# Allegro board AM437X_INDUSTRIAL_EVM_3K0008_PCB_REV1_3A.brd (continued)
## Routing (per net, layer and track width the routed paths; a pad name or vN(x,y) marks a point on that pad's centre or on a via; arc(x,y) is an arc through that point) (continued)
AM437X_MMC0_DAT3: length 77.9
  TOP w0.13: v1(71.12,59.69) 71.77,59.04 72.81,59.04 73.12,59.35 U11.B1 ; v1(73.79,11) 74.5,10.29 R239.1 ; v1(65.91,56.22) 65.57,55.88 65.15,55.88 63.88,54.61 R158.2
  L4_SIG2 w0.13: v1(79.48,10.64) 79.98,11.15 79.98,17.7 73.48,24.2 72.96,24.2 69.34,27.82 68.61,27.82 67.11,29.31 67.11,29.94 67.22,30.04 67.22,32.39 65.87,33.74 65.87,39.25 65.18,39.94 63.23,39.94 61.04,42.13 61.04,48.44 65.53,52.93 65.53,55.84 v1(65.91,56.22) 65.91,56.31 69.29,59.69 v1(71.12,59.69)
  BOTTOM w0.13: v1(73.79,11) 74.14,10.64 v1(79.48,10.64)
AM437X_MMC0_SDCD: length 9.1
  TOP w0.13: R84.2 83.31,82.68 83.31,80.01 83.19,79.88 83.19,78.99 82.29,78.1 82.29,77.59 82.28,77.58 82.28,75.63 81.78,75.14 U11.R25
AM437X_OSC0_IN: length 9.4
  TOP w0.13: R92.1 73.02,82.55 73.02,79.86 74.84,78.04 74.84,76.12 73.98,75.27 U11.C25
AM437X_OSC0_OUT: length 9.5
  TOP w0.13: U11.B25 74.6,76.22 74.6,77.95 74.12,78.43 72.48,80.07 R91.1
AM437X_PROFI_RXD: length 117.2
  TOP w0.13: v1(83.95,7.34) 82.85,7.34 J16.47 ; U11.K21 78.26,72.35 v1(78.09,72.52)
  L4_SIG2 w0.13: v1(78.08,81.67) 78.56,81.19 78.56,80.96 79.76,79.76 79.76,78.66 82.35,76.07 82.76,76.07 84.7,74.13 86.97,74.13 91.35,69.75 91.35,65.57 93.55,63.37 93.55,62.53 97.05,59.03 97.05,56.18 98.72,54.51 98.72,53.66 100.07,52.32 100.07,50.94 101.61,49.4 101.61,40.33 103.04,38.91 103.2,38.91 103.83,38.28 103.83,34.65 103.98,34.5 103.98,27 103.07,26.08 103.07,13.47 102.9,13.3 102.9,12.56 100.88,10.54 100.88,9.67 100.36,9.14 97.35,9.14 97.17,9.33 93.7,9.33 93.11,8.74 85.34,8.74 v1(83.95,7.34)
  BOTTOM w0.13: v1(78.08,81.67) 78.08,79.64 78.1,79.63 78.1,77 77.81,76.72 77.81,75.63 78.45,75 78.45,72.88 v1(78.09,72.52)
AM437X_PROFI_TXD: length 153.2
  TOP w0.13: U11.L21 79.4,72.35 v1(79.63,72.12)
  L3_SIG1 w0.13: v1(82.93,86.36) 82.93,84.33 82.68,84.07 82.68,82.57 83.46,81.78 83.46,80.47 83.24,80.24 83.24,79.04 80.64,76.45 80.64,72.39 80.38,72.12 v1(79.63,72.12)
  L4_SIG2 w0.13: v1(82.93,86.36) 83.06,86.36 85.78,83.64 86.03,83.64 88.23,81.44 91.68,81.44 92.4,80.72 92.4,80.72 97.42,75.7 97.42,72.91 98.34,71.99 98.34,67.91 99.35,66.9 99.35,64.94 100.07,64.22 102.48,64.22 103.18,63.52 103.36,63.52 106.17,60.71 108.31,60.71 110.44,58.58 110.44,55.71 110.04,55.31 110.04,54.83 110.98,53.9 110.98,50.04 111.97,49.05 111.97,45.91 112.54,45.34 112.54,37 113.85,35.69 113.85,34.57 115.86,32.56 115.86,29.11 111.2,24.45 110.81,24.06 110.81,21.07 109.76,20.02 109.76,8 110.33,7.44 110.33,3.44 109.58,2.69 93.07,2.69 92.33,3.43 92.33,6.35 91.62,7.06 84.57,7.06 J16.45
AM437X_PRU0_ENDAT0_CLK: length 27.8
  TOP w0.13: U11.N24 80.17,74.62 80.17,75.18 80.92,75.93 80.92,81.23 81.35,81.66 v1(81.35,81.91)
  L4_SIG2 w0.13: v2(87.63,77.6) 87.12,77.09 84.46,77.09 81.35,80.19 v1(81.35,81.91)
  BOTTOM w0.13: R427.2 R428.2 94.35,77.1 92.2,79.25 89.28,79.25 v2(87.63,77.6)
AM437X_PRU0_ENDAT0_OUT: length 18.3
  TOP w0.13: v1(81.6,73.47) 81.39,73.47 81.24,73.32 80.81,73.32 U11.N22
  L4_SIG2 w0.13: v2(86.87,77.6) 84.39,77.6 84.08,77.9 82.24,79.75 82.24,80.04 v1(81.89,80.39)
  BOTTOM w0.13: v2(86.87,77.6) 86.87,78.23 86.48,78.62 R422.2 R423.2 ; v1(81.89,80.39) 81.89,80.39 81.89,76.38 81.37,75.85 81.37,73.7 v1(81.6,73.47)
AM437X_PRU0_ENDAT0_OUTEN: length 215.6
  TOP w0.13: U11.H23 76.83,73.65 v1(76.66,73.48)
  L3_SIG1 w0.13: J16.35 94.33,4.86 94.33,3.44 93.51,2.62 68.86,2.62 66.45,5.03 62.56,5.03 61.08,3.55 54.05,3.55 53.37,2.86 48.5,2.86 47.61,3.75 42.48,3.75 40.13,6.1 28.01,6.1 25.3,8.81 25.3,13.41 32.38,20.49 v1(32.38,24.77)
  L4_SIG2 w0.13: v1(100.1,10.03) 100.1,11.37 102.45,13.72 102.45,26.34 103.37,27.25 103.37,33.59 102.35,34.61 102.35,38.73 100.99,40.08 100.99,49.14 99.45,50.68 99.45,52.06 98.11,53.41 98.11,54.25 96.43,55.93 96.43,58.78 92.93,62.28 92.93,63.12 90.73,65.32 90.73,69.09 87.4,72.42 87.01,72.42 86.66,72.76 86.66,73.42 86.41,73.67 84.5,73.67 82.66,75.52 80.85,75.52 78.36,78 v1(76.61,78)
  BOTTOM w0.13: v1(100.1,10.03) 100.99,9.14 101.75,9.14 102.13,8.76 102.13,7.85 101.57,7.29 98.93,7.29 98.6,6.96 94.46,6.96 J16.35 ; v1(32.38,24.77) 31.62,25.53 28.58,25.53 27.18,24.13 18.3,24.13 R526.2 ; v1(76.61,78) 76.66,77.95 v1(76.66,73.48)
AM437X_PRUETH0_COL: length 95.3
  TOP w0.13: v1(75.29,81.15) 74.93,80.8 74.93,79.54 75.3,79.17 75.3,75.93 74.64,75.27 U11.D25
  L3_SIG1 w0.13: v1(70.31,100.28) 70.68,100.65 70.68,102.83 70.19,103.32 69.63,103.32 65.82,107.13 61.66,107.13 58.68,104.15 44.62,104.15 43.1,105.66 29.72,105.66 v1(28.83,106.55)
  BOTTOM w0.13: v1(75.29,81.15) 75.29,81.79 75,82.07 75,83.97 74.28,84.69 74.28,85.94 69.9,90.32 69.9,99.88 v1(70.31,100.28) ; R351.2 33.27,91.57 32.1,91.57 31.69,91.97 31.69,92.99 30.61,94.07 30.61,101.6 28.83,103.38 v1(28.83,106.55)
AM437X_PRUETH0_CRS: length 65.9
  TOP w0.13: v1(76.15,72.13) 76.58,71.7 U11.G20 ; R65.2 v1(34.61,88.61)
  L3_SIG1 w0.13: v1(66.49,71.44) 66.54,71.44 66.54,71.48 66.47,71.48 66.47,71.43 66.47,71.43 65.81,72.09 65.13,72.09 63.4,70.36 61.56,70.36 59.28,68.07 57.44,68.07 56.84,68.67 56.17,68.67 54.49,70.35 54.23,70.35 50.49,74.08 47.58,74.08 44.71,76.95 35.06,76.95 v1(33.02,78.99)
  L4_SIG2 w0.13: v1(76.15,72.13) 76.12,72.16 76.12,73.48 75.17,74.44 74.37,74.44 72.26,72.33 67.32,72.33 66.49,71.49 v1(66.49,71.44)
  BOTTOM w0.13: v1(33.02,78.99) 33.38,78.99 34.24,79.85 34.24,80.36 36.17,82.29 36.17,83.24 34.81,84.59 34.81,88.41 v1(34.61,88.61)
AM437X_PRUETH0_MRCLK: length 87.2
  TOP w0.13: U11.C17 74.28,70.05 v1(74.28,70.16) ; v1(42.34,100.1) 42.34,90.98 40.89,89.53 36.45,89.53 35.69,88.77 35.69,87.63 34.42,86.36 R76.2
  L3_SIG1 w0.13: v1(61.62,89.36) 61.77,89.51 61.77,90.24 59.49,92.52 59.49,93.89 58.48,94.9 58.48,96.26 57.39,97.35 57.39,97.48 56.72,98.16 55.26,98.16 52.94,100.47 50.96,100.47 50.19,99.69 47.17,99.69 46.65,100.22 44.61,100.22 44.5,100.1 v1(42.34,100.1)
  L4_SIG2 w0.13: v1(61.62,89.36) 61.54,89.36 59.72,87.54 59.72,79.28 v1(58.29,77.85)
  BOTTOM w0.13: v1(74.28,70.16) 74.15,70.03 69.67,70.03 66.47,73.23 62.57,73.23 62.07,72.73 57.62,72.73 56.32,74.03 56.09,74.26 56.09,76.28 57.66,77.85 v1(58.29,77.85) ; U39.16 61.73,89.46 v1(61.62,89.36)
AM437X_PRUETH0_RXD0: length 88.2
  TOP w0.13: U11.B18 73.01,70.73 69.48,70.73 69.47,70.73 65.65,74.56 65.01,74.56 64.47,75.11 62.45,75.11 62.03,75.52 60.73,75.52 60.42,75.83 56.15,75.83 55.65,75.34 49.05,75.34 47.83,76.56 47.83,83.59 51.64,87.4 53.37,87.4 55.38,89.42 55.38,89.64 55.81,90.07 56.42,90.07 v1(58.42,92.06)
  L3_SIG1 w0.13: v1(58.42,92.06) 58.42,92.18 56.01,94.59 56.01,95.12 54.42,96.71 54.07,96.71 53.01,97.76 49.48,97.76 49,97.29 43.26,97.29 42.28,98.27 40.31,98.27 39.7,97.66 34.19,97.66 33.28,96.76 33.28,95.76 33.48,95.57 33.54,95.5 34.99,94.06 34.99,93.22 35.64,92.57 35.64,92.53 v1(35.86,92.3)
  BOTTOM w0.13: v1(35.86,92.3) 35.18,91.62 34.34,91.62 33.91,92.05 R349.2 ; U39.9 v1(58.42,92.06)
AM437X_PRUETH0_RXD1: length 88
  TOP w0.13: U11.A18 69.48,70.4 69.47,70.4 65.63,74.25 64.56,74.25 64.01,74.8 62.26,74.8 61.84,75.21 60.61,75.21 60.41,75.41 56.49,75.41 55.97,74.9 48.57,74.9 47.32,76.15 47.32,85.27 49.06,87.01 50.58,87.01 52.91,89.33 54.48,89.33 54.97,89.81 54.97,90.04 v1(55.62,90.7)
  L3_SIG1 w0.13: v1(55.62,90.7) 54.51,90.7 51.75,93.46 50.8,93.46 49.79,94.48 48.83,94.48 48.29,93.93 47.84,93.93 46.56,92.66 46.56,92.27 46.41,92.12 45.44,92.12 45.29,91.97 45.29,91.75 45.44,91.6 46.41,91.6 46.56,91.45 46.56,90.95 45.82,90.2 44.38,90.2 44.04,90.55 44.04,91.57 43.63,91.97 41.1,91.97 40.58,92.49 40.58,94.05 40.43,94.2 40.21,94.2 40.06,94.05 40.06,92.46 39.9,92.31 39.69,92.31 39.54,92.46 39.54,93.28 39.38,93.44 39.17,93.44 39.01,93.28 39.01,92.46 38.86,92.31 38.65,92.31 38.49,92.46 38.49,93.28 38.34,93.44 38.12,93.44 37.97,93.28 37.97,92.46 37.82,92.31 37.62,92.31 36.14,93.78 36.14,93.95 35.51,94.59 v1(35.13,94.59)
  BOTTOM w0.13: R344.2 35.13,94.56 v1(35.13,94.59) ; v1(55.62,90.7) 55.69,90.76 U39.7
AM437X_PRUETH0_RXD2: length 87.6
  TOP w0.13: v1(58.42,89.46) 57.38,89.46 53.06,85.14 50.98,85.14 50.16,84.33 50.16,80.64 50.65,80.16 51.12,80.16 51.24,80.28 51.24,80.68 51.35,80.8 51.51,80.8 51.63,80.68 51.63,80.28 51.74,80.16 51.9,80.16 52.02,80.28 52.02,80.68 52.13,80.8 52.29,80.8 52.41,80.68 52.41,80.28 52.52,80.16 53.75,80.16 57.32,76.59 61.43,76.59 61.57,76.73 63.73,76.73 65.29,75.18 65.79,75.18 69.58,71.38 69.58,71.38 73.01,71.38 U11.B19
  L3_SIG1 w0.13: v1(34.82,95.28) 34.54,95.55 34.54,96.91 34.83,97.19 36.18,97.19 38.65,94.73 39.08,94.73 39.59,95.24 39.59,96.03 40.3,96.74 43.03,96.74 43.19,96.59 43.19,95.74 43.34,95.59 43.55,95.59 43.71,95.74 43.71,96.59 43.86,96.74 44.08,96.74 44.23,96.59 44.23,95.74 44.38,95.59 44.6,95.59 44.75,95.74 44.75,96.59 44.9,96.74 45.12,96.74 45.27,96.59 45.27,95.74 45.42,95.59 45.64,95.59 45.79,95.74 45.79,96.59 45.94,96.74 46.16,96.74 46.31,96.59 46.31,95.74 46.47,95.59 46.68,95.59 46.83,95.74 46.83,96.59 46.99,96.74 48.84,96.74 49.18,96.39 50.3,96.39 51.18,97.27 51.71,97.27 53.84,95.14 53.84,94.61 54.38,94.08 55.89,94.08 56.81,93.15 56.81,89.8 57.14,89.46 v1(58.42,89.46)
  BOTTOM w0.13: R339.2 33.99,94.49 34.77,95.28 v1(34.82,95.28) ; U39.5 v1(58.42,89.46)
AM437X_PRUETH0_RXD3: length 87
  TOP w0.13: U11.A19 69.58,71.05 65.84,74.79 65.16,74.79 63.55,76.4 61.67,76.4 61.55,76.28 56.96,76.28 53.67,79.58 49.79,79.58 49.02,80.34 49.02,81.09 49.14,81.2 49.44,81.2 49.56,81.32 49.56,81.48 49.44,81.59 49.14,81.59 49.02,81.71 49.02,81.87 49.14,81.98 49.44,81.98 49.56,82.1 49.56,82.26 49.44,82.37 49.14,82.37 49.02,82.49 49.02,82.65 49.14,82.76 49.44,82.76 49.56,82.88 49.56,83.04 49.44,83.16 49.14,83.16 49.02,83.27 49.02,83.92 50.75,85.65 52.73,85.65 55.85,88.77 v1(55.85,89.45)
  L3_SIG1 w0.13: v1(35.03,96.72) 35.99,96.72 38.73,93.98 39.19,93.98 40.19,94.98 40.57,94.98 40.72,95.13 40.72,96 40.88,96.15 41.09,96.15 41.24,96 41.24,95.13 41.4,94.98 41.61,94.98 41.77,95.13 41.77,96 41.92,96.15 42.13,96.15 42.29,96 42.29,95.13 42.44,94.98 43.61,94.98 43.83,94.77 43.83,93.66 44.06,93.42 45.25,93.42 45.47,93.64 45.47,94.95 45.67,95.15 46.02,95.15 46.2,94.97 46.2,93.47 46.35,93.32 46.57,93.32 46.72,93.47 46.72,94.18 46.9,94.37 48.11,94.37 48.65,94.91 49.97,94.91 50.98,93.9 51.73,93.9 51.76,93.92 51.76,94.85 51.91,95 52.13,95 52.28,94.85 52.28,93.92 52.43,93.77 52.66,93.77 52.81,93.62 52.81,93.01 52.97,92.86 53.18,92.86 53.33,93.01 53.33,93.24 53.45,93.36 55.99,93.36 56.36,92.99 56.36,89.76 56.05,89.45 v1(55.85,89.45)
  BOTTOM w0.13: v1(35.03,96.72) 34.85,96.55 34.82,96.55 R337.2 ; v1(55.85,89.45) 55.85,88.52 56.21,88.16 U39.3
AM437X_PRUETH0_RXDV: length 88.4
  TOP w0.13: R67.2 34.52,87.5 35.1,88.09 35.1,89.88 37.03,91.81 38.49,91.81 41.05,94.36 41.05,99.36 v1(40.2,100.21) ; v1(61.72,88.39) 61.98,88.14 R63.2 ; v1(74.75,70.55) 74.75,69.87 U11.D17
  L3_SIG1 w0.13: v1(61.72,88.39) 60.55,89.56 60.55,90.75 57.57,93.74 57.57,95.36 55.76,97.17 54.71,97.17 54.68,97.14 54.25,97.14 52.46,98.93 51.94,98.93 51.67,99.2 51.16,99.2 50.89,98.93 45.57,98.93 45.41,98.78 45.41,97.94 45.26,97.79 45.05,97.79 44.89,97.94 44.89,98.78 44.74,98.93 40.67,98.93 40.2,99.4 v1(40.2,100.21)
  L4_SIG2 w0.13: v1(59.56,77.34) 59.56,78.51 60.15,79.09 60.15,87.36 61.19,88.39 v1(61.72,88.39)
  BOTTOM w0.13: U39.18 61.95,88.16 v1(61.72,88.39) ; v1(59.56,77.34) 58.91,77.34 57.66,76.09 57.66,74.14 57.97,73.82 58.41,73.82 58.77,74.19 59.12,74.19 60.17,75.23 61.82,75.23 62.55,74.51 65.97,74.51 69.48,71 73.94,71 73.97,70.97 74.34,70.97 v1(74.75,70.55)
AM437X_PRUETH0_RXER: length 87.7
  TOP w0.13: v1(74.53,72.32) 74.32,72.11 74.32,71.36 U11.D19 ; v1(38.88,100.21) 40.61,98.48 40.61,94.59 38.48,92.46 37.07,92.46 34.37,89.76 R59.2
  L3_SIG1 w0.13: v1(61.75,90.93) 60.23,92.45 60.23,92.63 60.34,92.75 61.81,92.75 61.92,92.86 61.92,93.02 61.81,93.14 60.34,93.14 60.23,93.25 60.23,93.41 60.34,93.53 61.81,93.53 61.92,93.64 61.92,93.81 61.81,93.92 60.34,93.92 60.23,94.03 60.23,95.85 58.93,97.16 58.93,98.04 57.42,99.55 54.48,99.55 52.75,101.28 49.01,101.28 47.86,100.14 47.39,100.14 46.58,100.94 41.71,100.94 41.55,100.79 41.55,99.54 41.4,99.39 41.19,99.39 41.03,99.54 41.03,100.79 40.88,100.94 39.12,100.94 38.88,100.7 v1(38.88,100.21)
  L4_SIG2 w0.13: v1(61.75,90.93) 62.73,89.94 62.73,78.99 v1(61.98,78.23)
  BOTTOM w0.13: v1(61.75,90.93) 61.92,90.76 U39.14 ; v1(74.53,72.32) 74.49,72.28 69.91,72.28 66.8,75.39 66.8,77.5 66.29,78 65,78 64.64,78.36 62.1,78.36 v1(61.98,78.23)
AM437X_PRUETH0_RXLINK: length 38.6
  TOP w0.13: U11.C19 73.82,70.88 v1(73.82,70.55)
  L4_SIG2 w0.13: v1(61.64,74.74) 62.57,74.74 63.39,75.55 63.39,75.55 63.53,75.69 63.53,79.53 63.17,79.88 63.17,82.05 65.19,84.07 65.19,89.75 62.88,92.06 v1(61.72,92.06)
  BOTTOM w0.13: U39.12 v1(61.72,92.06) ; R434.2 61.53,74.74 v1(61.64,74.74) 62.34,74.04 66.1,74.04 69.59,70.55 v1(73.82,70.55)
AM437X_PRUETH0_TXCLK: length 17.7
  TOP w0.13: U11.B22 73.03,73.31 72.56,73.31 72.51,73.26 69.67,73.26 66.94,75.99 66.94,76.66 66.36,77.24 66.36,79.94 v1(66.06,80.24) ; v1(64.31,80.61) 64.12,80.61 64.06,80.67 U9.3 v1(61.72,80.67)
  BOTTOM w0.13: v1(66.06,80.24) 66.06,80.34 65.72,80.67 64.54,80.67 64.48,80.61 v1(64.31,80.61) ; v1(61.72,80.67) 60.99,80.67 R410.2
AM437X_PRUETH0_TXD0: length 28.6
  TOP w0.13: U11.B20 73.03,72.01 72.56,72.01 72.49,71.94 69.69,71.94 69.59,72.03 65.69,75.92 65.69,76 62.96,78.73 56.42,78.73 55.26,79.9 55.26,82.4 56.13,83.27 U9.14 58.33,83.27 v1(58.42,83.19)
  BOTTOM w0.13: v1(58.42,83.19) 58.29,83.31 R391.2
AM437X_PRUETH0_TXD1: length 30.2
  TOP w0.13: v1(58.42,84.57) U9.12 56.13,84.57 55.76,84.2 55.59,84.2 55.24,83.85 55.24,83.01 54.82,82.58 54.82,79.72 57.16,77.38 58.78,77.38 59.21,77.81 60.74,77.81 60.87,77.69 63.39,77.69 65.67,75.41 65.88,75.41 69.59,71.7 69.59,71.7 U11.A20
  BOTTOM w0.13: v1(58.42,84.57) 57.54,84.57 R378.2
AM437X_PRUETH0_TXD2: length 23.9
  TOP w0.13: U11.C21 73.98,72.43 74.27,72.72 74.34,72.72 74.36,72.74 74.91,72.74 v1(74.99,72.81) ; v1(61.72,84.57) U9.9 62.98,84.58 64.21,84.58 64.72,84.07 64.72,83.24 65.81,82.15 66.39,82.15 66.8,81.74 66.8,78.63 v1(66.78,78.61)
  BOTTOM w0.13: v1(66.78,78.61) 66.8,78.59 66.8,77.96 67.24,77.52 67.24,76.98 67.79,76.43 67.79,75.61 70.88,72.52 74.14,72.52 74.36,72.74 74.54,72.74 74.54,72.74 74.91,72.74 v1(74.99,72.81) ; R377.2 61.71,84.58 v1(61.72,84.57)
AM437X_PRUETH0_TXD3: length 20.4
  TOP w0.13: v1(61.72,83.27) U9.7 64.07,83.27 65.21,82.13 65.21,80.24 64.7,79.72 64.7,78.25 66.2,76.74 66.2,76.08 69.69,72.58 72.48,72.58 72.56,72.66 73.03,72.66 U11.B21
  BOTTOM w0.13: R390.2 61,83.27 v1(61.72,83.27)
AM437X_PRUETH0_TXEN: length 19.4
  TOP w0.13: U11.A21 72.6,72.26 69.7,72.26 69.59,72.35 65.97,75.98 65.97,76.36 64.26,78.07 64.26,79.9 64.78,80.42 64.78,81.27 64.08,81.97 U9.5 v1(61.72,81.97)
  BOTTOM w0.13: R404.2 61.78,81.91 v1(61.72,81.97) 61.67,81.91 R405.2
AM437X_PRUETH1_MRCLK: length 47.5
  TOP w0.13: v1(75.52,62.24) 75.88,62.6 U11.F6 ; v1(66.8,60.92) 66.28,60.4 59.41,60.4 58.56,59.55 55.28,59.55 55.21,59.62 49.09,59.62 46.74,61.98 v1(41.53,61.98)
  BOTTOM w0.13: 65.91,61.09 66.63,61.09 v1(66.8,60.92) 68.62,62.74 72.26,62.74 72.47,62.53 75.02,62.53 75.31,62.24 v1(75.52,62.24) ; v1(41.53,61.98) 41.53,60.83 40.77,60.07 36.58,60.07 35.56,61.09 R466.2
AM437X_PRUETH1_RXD0: length 55.3
  TOP w0.13: v1(35.94,67.41) 36.86,67.41 37.01,67.26 37.01,65.71 37.17,65.55 37.38,65.55 37.53,65.71 37.53,68.02 37.69,68.18 37.9,68.18 38.05,68.02 38.05,65.71 38.21,65.55 38.42,65.55 38.58,65.71 38.58,67.26 38.73,67.41 39.2,67.41 39.53,67.09 39.53,66.87 39.12,66.47 39.12,66.25 39.28,66.1 39.49,66.1 39.9,66.5 40.11,66.5 42.13,64.49 43.54,64.49 44.27,63.75 46.35,63.75 49.46,60.65 58.01,60.65 58.95,61.59 61.59,61.59 62.23,60.96 65.74,60.96 66.8,62.03 67.64,62.03 68.02,62.41 69.9,62.41 71.05,63.56 74.29,63.56 74.46,63.72 U11.D8
  BOTTOM w0.13: R447.2 34.39,67.41 v1(35.94,67.41)
AM437X_PRUETH1_RXD1: length 52
  TOP w0.13: U11.G8 76.38,63.69 v1(76.38,63.05) ; v1(59.44,62.23) 58.93,62.23 57.78,61.09 49.66,61.09 47.31,63.44 47.29,63.44 46.54,64.19 44.5,64.19 43.61,65.07 42.88,65.07 39.29,68.67 39.07,68.67 38.77,68.37 38.55,68.37 38.4,68.52 38.4,68.74 38.7,69.04 38.7,69.26 38.55,69.41 38.33,69.41 38.03,69.11 37.81,69.11 37.66,69.26 37.66,69.47 37.96,69.78 37.96,69.99 37.68,70.28 36.14,70.28 35.69,69.82 v1(35.69,69.26)
  BOTTOM w0.13: v1(76.38,63.05) 75.97,63.46 71.81,63.46 71.79,63.47 67.05,63.47 66.87,63.66 62.99,63.66 62.32,62.99 61.85,62.99 61.09,62.23 v1(59.44,62.23) ; v1(35.69,69.26) 35.02,68.59 34.43,68.59 R445.2
AM437X_PRUETH1_RXD2: length 54.6
  TOP w0.13: v1(36.32,69.73) 36.32,68.71 35.47,67.85 35.47,67.15 35.87,66.74 35.88,66.74 36.2,66.43 36.2,65.79 35.85,65.44 35.85,64.29 37.16,62.97 37.58,62.97 37.73,63.12 37.73,63.84 37.88,64 38.1,64 38.25,63.84 38.25,63.12 38.4,62.97 38.62,62.97 38.77,63.12 38.77,63.84 38.92,64 39.14,64 39.29,63.84 39.29,63.12 39.44,62.97 39.77,62.97 40.13,62.61 40.13,61.73 41.92,59.93 47.11,59.93 49.17,57.88 62.4,57.88 63.07,58.55 64.76,58.55 64.93,58.71 66.61,58.71 68.65,60.75 69.23,60.75 70.1,61.62 73.01,61.62 U11.B4
  BOTTOM w0.13: R443.2 34.43,69.73 v1(36.32,69.73)
AM437X_PRUETH1_RXD3: length 49.9
  TOP w0.13: v1(61.71,62.09) 61.69,62.1 60.23,62.1 59.63,62.7 58.78,62.7 57.6,61.52 49.86,61.52 47.75,63.63 47.73,63.63 46.74,64.62 44.85,64.62 40.86,68.61 40.86,69.61 40.48,69.99 40.26,69.99 39.82,69.55 39.6,69.55 39.45,69.7 39.45,69.92 39.89,70.36 39.89,70.58 39.62,70.84 v1(35.94,70.84) ; v1(75.48,62.81) 75.53,62.86 75.55,62.86 U11.F7
  BOTTOM w0.13: v1(61.71,62.09) 62.07,61.72 66.67,61.72 67.95,62.99 72.34,62.99 72.52,62.81 v1(75.48,62.81) ; R441.2 34.43,70.88 35.91,70.88 v1(35.94,70.84)
AM437X_PRUETH1_RXDV: length 51.2
  TOP w0.13: v1(36.32,64.52) 36.83,65.02 39.21,65.02 39.6,64.63 39.82,64.63 40.44,65.26 40.66,65.26 40.81,65.11 40.81,64.89 40.19,64.26 40.19,64.05 40.56,63.67 40.56,61.93 42.12,60.37 47.29,60.37 49.11,58.55 v1(61.05,58.55) ; U11.C5 v1(73.78,61.53)
  BOTTOM w0.13: v1(73.78,61.53) 73.22,60.96 68.45,60.96 67.18,59.69 65.91,59.69 65.53,60.07 63.09,60.07 62.32,59.3 62.32,58.35 62.04,58.08 61.52,58.08 v1(61.05,58.55) ; R459.1 R461.2 34.8,62.23 36.32,63.75 v1(36.32,64.52)
AM437X_PRUETH1_RXER: length 57.9
  TOP w0.13: U11.B3 73.03,60.96 72.59,60.96 72.39,61.16 70.29,61.16 69.33,60.19 68.75,60.19 66.4,57.84 66.14,57.84 65.87,57.57 65.87,57.57 65.47,57.18 63.34,57.18 63.09,56.93 59.58,56.93 58.92,56.27 58.42,56.27 58.27,56.42 58.27,56.77 58.11,56.92 57.9,56.92 57.75,56.77 57.75,56.22 57.59,56.07 57.38,56.07 57.23,56.22 57.23,57.12 57.07,57.28 56.86,57.28 56.7,57.12 56.7,56.22 56.55,56.07 55.98,56.07 54.69,57.36 49.07,57.36 46.93,59.5 41.25,59.5 41.1,59.65 41.1,60.11 40.95,60.26 40.73,60.26 40.58,60.11 40.58,59.3 40.43,59.14 40.21,59.14 40.06,59.3 40.06,60.18 39.91,60.34 39.69,60.34 39.54,60.18 39.54,59.25 39.38,59.09 39.17,59.09 39.02,59.25 39.02,60.18 38.86,60.34 38.65,60.34 38.49,60.18 38.49,59.65 38.34,59.5 37.69,59.5 36.67,60.52 36.67,60.69 36.82,60.85 37.36,60.85 37.52,61 37.52,61.22 37.36,61.37 36.82,61.37 36.67,61.52 36.67,61.74 36.82,61.89 37.36,61.89 37.52,62.04 37.52,62.26 37.36,62.41 36.82,62.41 36.67,62.56 36.67,62.85 35.84,63.68 35.38,63.68 35.22,63.85 34.22,63.85 33.91,64.16 R136.2
AM437X_PRUETH1_TXCLK: length 76.7
  TOP w0.13: R241.2 77.34,11.3 76.83,11.81 v1(75.06,11.81) ; v1(75,64.34) 75,64.19 U11.E8 ; R141.2 v1(65.15,62.23)
  L3_SIG1 w0.13: v1(75,64.34) 74.72,64.06 70.28,64.06 69.22,62.99 65.91,62.99 v1(65.15,62.23)
  L4_SIG2 w0.13: v1(65.15,62.23) 65.15,61.63 63.77,60.26 63.77,57.22 62.08,55.54 62.08,54.26 58.38,50.55 58.38,33.89 58.85,33.42 59.14,33.42 61.69,30.87 61.69,29.98 63.01,28.66 63.01,26.38 63.67,25.72 65.15,25.72 75.06,15.81 v1(75.06,11.81)
AM437X_PRUETH1_TXD0: length 14.8
  TOP w0.13: v1(75.06,61.9) 74.98,61.98 74.98,62.94 U11.E7
  BOTTOM w0.13: v1(75.06,61.9) 74.99,61.84 74.96,61.84 73.83,60.71 68.58,60.71 67.31,59.44 66.55,59.44 65.02,57.91 R471.2 R469.2
AM437X_PRUETH1_TXD1: length 16.4
  TOP w0.13: U11.D7 74.33,62.94 70.77,62.94 69.15,61.33 68.57,61.33 66.93,59.69 61.98,59.69 R150.2 61.59,58.8 v1(61.85,58.55)
  BOTTOM w0.13: R150.2 61.59,58.8 v1(61.85,58.55)
AM437X_PRUETH1_TXD2: length 9.6
  TOP w0.13: U11.A4 72.6,61.39 70.2,61.39 69.31,60.5 68.73,60.5 66.51,58.28 65.21,58.28 64.81,57.88 R153.2
AM437X_PRUETH1_TXD3: length 10.8
  TOP w0.13: U11.C6 73.64,62.26 70.41,62.26 69.16,61.01 68.58,61.01 66.72,59.15 R151.2
AM437X_PRUETH1_TXEN: length 16.4
  TOP w0.13: U11.C3 73.68,60.34 72.55,60.34 72.2,60.69 70.48,60.69 69.47,59.68 68.9,59.68 66.46,57.24 66.46,56.98 66.13,56.64 64.26,56.64 63.25,55.63 R155.2 R157.1
AM437X_PRUETH_MDCLK: length 146.4
  TOP w0.13: v1(59.94,68.07) 60.43,67.58 63.01,67.58 63.41,67.97 64.87,67.97 65.23,67.61 67.06,67.61 68.17,66.5 U11.A12 ; v1(25.78,82.8) 26.67,83.69 26.67,85.72 ; R147.2 v1(26.67,59.69)
  L3_SIG1 w0.13: v1(24.64,76.45) 24.64,76.46 21.46,76.46 20,77.92 20,79.56 20.83,80.39 21.8,80.39 21.95,80.24 21.95,78.99 22.1,78.84 22.32,78.84 22.47,78.99 22.47,80.24 22.62,80.39 22.84,80.39 22.99,80.24 22.99,78.99 23.15,78.84 23.36,78.84 23.51,78.99 23.51,80.24 23.67,80.39 23.88,80.39 24.04,80.24 24.04,78.99 24.19,78.84 24.4,78.84 24.56,78.99 24.56,80.24 24.71,80.39 24.93,80.39 25.08,80.24 25.08,78.99 25.23,78.84 25.45,78.84 25.6,78.99 25.6,80.24 25.75,80.39 26.07,80.39 26.22,80.24 26.22,79.02 26.37,78.87 26.59,78.87 26.74,79.02 26.74,80.24 26.89,80.39 27.11,80.39 27.26,80.24 27.26,79.02 27.42,78.87 27.63,78.87 27.78,79.02 27.78,80.24 27.94,80.39 28.66,80.39 29,80.06 29.21,80.06 29.91,80.75 30.12,80.75 30.27,80.6 30.27,80.38 29.58,79.69 29.58,79.47 29.73,79.32 29.95,79.32 30.64,80.01 30.86,80.01 31.01,79.86 31.01,79.64 30.32,78.95 30.32,78.73 30.47,78.58 30.69,78.58 31.38,79.27 31.6,79.27 31.75,79.12 31.75,78.91 31.06,78.21 31.06,78 31.21,77.84 31.42,77.84 32.12,78.54 32.33,78.54 32.49,78.38 32.49,78.17 31.79,77.48 31.79,77.26 33.36,75.69 36.7,75.69 36.87,75.52 44.11,75.52 46.35,73.28 46.35,72.14 46.89,71.6 51.84,71.6 52.96,70.48 53.22,70.22 53.22,69.46 53.59,69.1 54.34,69.1 55.88,67.56 59.44,67.56 v1(59.94,68.07)
  L4_SIG2 w0.13: v1(26.67,59.69) 27.18,59.18 27.65,59.18 27.8,59.33 27.8,59.79 27.95,59.94 28.17,59.94 28.32,59.79 28.32,59.33 28.48,59.18 28.69,59.18 28.84,59.33 28.84,59.79 29,59.94 29.21,59.94 29.36,59.79 29.36,59.33 29.52,59.18 29.8,59.18 30.88,60.26 31.86,60.26 32.67,61.07 32.67,63.5 31.12,65.05 31.12,66.94 30.96,67.09 29.49,67.09 29.34,67.25 29.34,67.46 29.49,67.62 30.96,67.62 31.12,67.77 31.12,67.98 30.96,68.14 29.49,68.14 29.34,68.29 29.34,68.51 29.49,68.66 30.96,68.66 31.12,68.81 31.12,69.03 30.96,69.18 29.49,69.18 29.34,69.33 29.34,69.55 29.49,69.7 30.96,69.7 31.12,69.85 31.12,70.07 30.96,70.22 29.49,70.22 29.34,70.37 29.34,70.59 29.49,70.74 30.96,70.74 31.12,70.9 31.12,73.32 27.98,76.45 v1(24.64,76.45) 25.78,77.6 v1(25.78,82.8)
AM437X_PRUETH_MDDATA: length 138.7
  TOP w0.13: 25.65,85.72 25.65,84.01 v1(25.53,83.88) ; U11.D24 74.98,74.64 74.98,75.28 75.53,75.83 75.53,80.13 v1(75.35,80.31) ; R146.2 26.15,59.83 26.15,59.24 v1(25.53,58.61)
  L4_SIG2 w0.13: v1(25.53,58.61) 30.85,58.61 32.98,60.74 32.98,63.63 31.42,65.18 31.42,73.48 26.92,77.98 26.92,82.49 v1(25.53,83.88) 25.53,90.68 23.76,92.45 23.76,103.13 25.4,104.78 26.29,104.78 27.17,103.9 28.61,103.9 30.61,101.9 42.77,101.9 43.22,102.35 43.39,102.52 43.78,102.91 51.52,102.91 52.08,102.35 60.16,102.35 60.81,103 66.47,103 67.3,102.17 67.3,102.17 67.75,101.71 67.75,101.71 68.25,101.22 v1(69.22,101.22)
  BOTTOM w0.13: v1(75.35,80.31) 75.35,80.42 74.84,80.94 74.23,80.94 73.95,81.21 73.95,81.6 74.69,82.35 74.69,83.84 73.97,84.56 73.97,85.81 69.6,90.19 69.6,99.06 69.22,99.44 v1(69.22,101.22)
AM437X_QSPI_CLK: length 9.3
  TOP w0.13: R128.2 65.04,67.04 67.02,67.04 67.88,66.18 73.01,66.18 U11.B12
AM437X_QSPI_CSN: length 9
  TOP w0.13: U11.A8 70.88,63.9 69.7,62.71 67.16,62.71 66.04,61.59 R144.2
AM437X_QSPI_D0: length 12.5
  TOP w0.13: U11.A9 70.17,64.55 69.16,63.54 65.22,63.54 65.05,63.71 63.41,63.71 62.73,64.39 R137.2
AM437X_QSPI_D1: length 12.3
  TOP w0.13: U11.E10 75.32,65.2 75.41,65.11 v1(75.41,64.73)
  BOTTOM w0.13: v1(75.41,64.73) 74.73,65.41 73.1,65.41 72.68,65.82 68.08,65.82 67.54,66.37 67.01,66.37 66.46,66.92 65.86,66.92 65.71,66.78 64.74,66.78 R449.2
AM437X_QSPI_D2: length 11.3
  TOP w0.13: v1(74.57,64.72) 74.63,64.79 74.63,65.02 74.64,65.02 U11.D10
  BOTTOM w0.13: R457.2 64.77,64.26 65.66,64.26 66.51,65.11 72.26,65.11 73.03,64.35 74.19,64.35 v1(74.57,64.72)
AM437X_QSPI_D3: length 10
  TOP w0.13: U11.C10 73.98,65 v1(73.76,64.77)
  BOTTOM w0.13: R453.2 64.77,65.41 72.49,65.41 73.12,64.77 v1(73.76,64.77)
AM437X_RGMII1_RD0: length 49.5
  TOP w0.13: v1(41.91,84.33) 41.91,83.82 42.19,83.54 44.2,83.54 44.4,83.34 44.4,83.08 44.4,83.07 44.4,82.58 44.16,82.34 43.78,82.34 43.59,82.14 43.59,81.15 43.74,81 44.08,81 44.39,80.69 44.39,77 47.8,73.59 54.03,73.59 54.24,73.38 56.06,73.38 56.97,74.3 v1(58.17,74.3) ; U11.F17 75.84,69.85 75.84,70.47 v1(75.82,70.48)
  BOTTOM w0.13: v1(58.17,74.3) 58.17,74.54 58.14,74.56 58.14,75.59 58.83,76.28 61.42,76.28 62.75,74.94 65.86,74.94 69.49,71.31 73.96,71.31 74.07,71.2 75.11,71.2 v1(75.82,70.48) ; R370.2 v1(41.91,84.33)
AM437X_RGMII1_RD1: length 51.9
  TOP w0.13: v1(44.2,84.33) 44.2,84.96 43.92,85.24 41.73,85.24 41.27,84.79 41.27,83.19 41.48,82.98 42.72,82.98 43.08,82.63 43.08,80.6 43.23,80.44 43.79,80.44 43.94,80.29 43.94,80.08 43.79,79.92 43.23,79.92 43.08,79.77 43.08,79.56 43.23,79.4 43.79,79.4 43.94,79.25 43.94,79.03 43.79,78.88 43.23,78.88 43.08,78.73 43.08,78.51 43.23,78.36 43.79,78.36 43.94,78.21 43.94,77.99 43.79,77.84 43.23,77.84 43.08,77.69 43.08,77.57 47.49,73.16 53.85,73.16 54.08,72.92 56.22,72.92 57.04,73.75 60.55,73.75 60.77,73.53 63.63,73.53 63.96,73.2 65.66,73.2 69.43,69.43 73.01,69.43 U11.B16
  BOTTOM w0.13: R368.2 v1(44.2,84.33)
AM437X_RGMII1_RD2: length 49.3
  TOP w0.13: v1(55.57,74.17) 55.24,73.84 54.4,73.84 54.21,74.03 47.98,74.03 44.83,77.17 44.83,80.81 44.98,80.96 45.87,80.96 46.02,81.11 46.02,81.33 45.87,81.48 44.98,81.48 44.83,81.63 44.83,81.85 44.98,82 45.87,82 46.02,82.16 46.02,82.37 45.87,82.52 44.98,82.52 44.83,82.68 44.83,82.89 44.98,83.05 45.94,83.05 46.08,83.19 46.08,83.41 45.93,83.57 45.44,83.57 45.34,83.67 v1(45.34,84.33) ; v1(75.33,68.62) 75.33,69.05 U11.E16
  BOTTOM w0.13: v1(45.34,84.33) R367.2 ; v1(55.57,74.17) 57.47,72.26 59.05,72.26 59.52,71.79 61.74,71.79 62.75,72.8 66.27,72.8 69.47,69.6 74.36,69.6 v1(75.33,68.62)
AM437X_RGMII1_RD3: length 48.1
  TOP w0.13: v1(46.48,80.26) 45.42,80.26 45.27,80.11 45.27,79.62 45.42,79.47 46.41,79.47 46.56,79.31 46.56,79.1 46.41,78.94 45.42,78.94 45.27,78.79 45.27,78.58 45.42,78.42 46.41,78.42 46.56,78.27 46.56,78.06 46.41,77.9 45.42,77.9 45.27,77.75 45.27,77.35 45.46,77.16 46.28,77.16 46.41,77.04 46.41,76.21 48.16,74.46 54.44,74.46 v1(54.48,74.42) ; U11.C14 73.98,67.98 v1(74.22,68.22)
  BOTTOM w0.13: v1(54.48,74.42) 54.48,73.66 57.57,70.58 58.43,70.58 58.52,70.49 63.37,70.49 63.37,70.48 67.29,70.48 68.94,68.83 72.93,68.83 73.66,68.11 73.91,68.11 74.03,68.22 v1(74.22,68.22) ; R365.2 47.62,81.41 v1(46.48,80.26)
AM437X_RGMII1_RXCLK: length 48
  TOP w0.13: U11.D13 74.31,66.82 v1(74.31,66.81) ; v1(56.64,68.2) 56.26,68.58 48.13,68.58 45.09,71.63 45.09,74.17 38.99,80.26 38.99,83.82 v1(38.48,84.33)
  BOTTOM w0.13: v1(56.64,68.2) 57.26,67.58 60.87,67.58 61.05,67.77 66.55,67.77 67.13,67.18 67.79,67.18 68.17,66.81 v1(74.31,66.81) ; v1(38.48,84.33) R373.2
AM437X_RGMII1_RXCTL: length 52.1
  TOP w0.13: v1(40.77,84.33) 40.77,82.93 41.15,82.55 42.42,82.55 42.62,82.35 42.62,81 42.47,80.85 41.43,80.85 41.27,80.7 41.27,80.48 41.43,80.33 42.47,80.33 42.62,80.18 42.62,79.96 42.47,79.81 41.43,79.81 41.27,79.66 41.27,79.44 41.43,79.29 42.47,79.29 42.62,79.13 42.62,77.39 47.29,72.72 53.62,72.72 53.87,72.47 56.41,72.47 57.29,71.59 57.74,71.59 57.89,71.74 57.89,72.49 58.04,72.64 58.26,72.64 58.41,72.49 58.41,71.74 58.57,71.59 58.78,71.59 58.93,71.74 58.93,72.49 59.09,72.64 59.3,72.64 59.46,72.49 59.46,71.74 59.61,71.59 59.85,71.59 59.94,71.5 61.6,71.5 61.75,71.65 61.75,71.98 61.91,72.14 62.12,72.14 62.27,71.98 62.27,71.65 62.43,71.5 65.26,71.5 66.17,70.59 67.03,70.59 69.17,68.45 U11.A15
  BOTTOM w0.13: v1(40.77,84.33) R371.2
AM437X_RGMII1_TD0: length 10.4
  TOP w0.13: R102.2 65.14,72.23 65.97,71.4 65.97,71.25 66.27,70.94 67.13,70.94 69.3,68.78 73.01,68.78 U11.B15
AM437X_RGMII1_TD1: length 11.8
  TOP w0.13: R107.2 61.97,70.42 65.08,70.42 65.56,69.95 66.73,69.95 68.88,67.8 U11.A14
AM437X_RGMII1_TD2: length 10.3
  TOP w0.13: R123.2 64.78,68.67 65.32,68.14 67.01,68.14 68.33,66.82 73.66,66.82 U11.C13
AM437X_RGMII1_TD3: length 10.8
  TOP w0.13: v1(73.82,68.6) 73.98,68.77 U11.C16
  BOTTOM w0.13: R439.2 66.01,71.12 66.21,70.93 67.36,70.93 69.2,69.09 73.33,69.09 v1(73.82,68.6)
AM437X_RGMII1_TXCLK: length 11.9
  TOP w0.13: U11.D14 74.64,67.83 v1(74.97,68.17)
  BOTTOM w0.13: R442.2 67.06,69.85 68.59,68.31 72.9,68.31 73.44,67.77 74.57,67.77 v1(74.97,68.17)
AM437X_RGMII1_TXCTL: length 11.7
  TOP w0.13: U11.A13 68.56,67.15 66.93,68.78 65.33,68.78 64.83,69.28 63.37,69.28 63.24,69.41 62.04,69.41 R121.2
AM437X_SD_CLKOUT: length 111.2
  TOP w0.13: v1(120.52,9.4) R263.2 ; U11.AD25 87.88,75.2 87.88,76.56 88.6,77.28 88.6,79.33 90.56,81.28 90.56,83.44 v1(91.19,84.07)
  L4_SIG2 w0.13: v1(91.19,84.07) 91.49,84.07 97.49,78.08 97.49,77.22 98.42,76.28 98.42,75.26 99.57,74.11 99.57,69.88 99.26,69.57 99.26,68.3 100.12,67.43 100.57,67.43 103.56,64.45 105.32,64.45 105.89,63.88 106.5,63.27 107.69,63.27 109.08,61.87 110.31,61.87 113.51,58.67 113.51,57.25 113.25,56.98 113.25,51.45 114.04,50.65 114.04,44.44 114.4,44.08 114.4,39.19 115.67,37.92 115.67,34.63 116.79,33.52 116.79,29.5 116.79,28.73 112.84,24.78 112.13,24.07 111.74,23.69 111.74,17.58 111.12,16.97 111.12,12.07 115.08,8.11 119.23,8.11 v1(120.52,9.4)
AM437X_SD_DATA_IN1: length 119.1
  TOP w0.13: R262.2 120.4,10.54 v1(121.03,10.54) ; v1(96.9,84.71) 96.9,82.93 94.44,80.47 94.44,74.66 93.67,73.89 93.67,73.53 92.93,72.79 92.93,72.52 92.76,72.35 U11.AE21
  L4_SIG2 w0.13: v1(121.03,10.54) 121.03,17.79 122.32,19.08 122.32,26.21 126.35,30.24 126.35,42.11 126.8,42.56 126.8,47.26 126.29,47.77 126.29,58.93 123.55,61.67 123.55,64.29 123.9,64.64 123.9,66.96 121.04,69.82 116.29,69.82 113.49,72.62 113.49,72.82 112.9,73.41 106.14,73.41 104.18,75.36 102.67,75.36 102.57,75.26 101.53,75.26 100.85,75.94 100.85,78.17 99.79,79.22 98.76,79.22 97.41,80.57 97.41,84.2 v1(96.9,84.71)
AM437X_SPI0_CS0N: length 120.5
  TOP w0.13: v1(81.96,72.18) 82.43,71.71 U11.T20
  L4_SIG2 w0.13: v1(83.82,82.3) 84.81,83.28 85.88,83.28 88.03,81.13 91.56,81.13 92.09,80.6 92.09,80.59 97.11,75.57 97.11,72.78 98.03,71.86 98.03,67.78 99.04,66.77 99.04,64.81 99.94,63.91 102.35,63.91 105.86,60.41 107.08,60.41 108.01,59.48 108.01,56.34 110.67,53.68 110.67,49.91 111.66,48.92 111.66,45.79 112.14,45.31 112.14,38.96 111.31,38.14 111.31,36.47 111.65,36.13 112,36.13 112.46,35.67 112.46,33.73 111.61,32.88 111.61,29.76 111.61,25.3 110.89,24.58 110.5,24.19 110.5,21.19 109.46,20.15 109.46,14.08 v1(109.22,13.84)
  BOTTOM w0.13: J16.30 100.37,4.86 101.75,4.86 102.33,5.44 102.33,6.35 105.45,9.47 105.45,14.42 105.76,14.73 108.33,14.73 v1(109.22,13.84) ; v1(81.96,72.18) 82.39,72.61 82.39,73.65 82.44,73.69 82.44,74.17 82,74.62 82,75.27 82.52,75.79 82.52,79.78 83.24,80.49 83.24,81.43 83.82,82.01 v1(83.82,82.3) 83.82,82.42 R384.2
AM437X_SPI0_D1: length 114.5
  TOP w0.13: v1(83.76,73.07) 83.76,73.07 83.38,72.69 82.78,72.69 U11.T21 ; v1(106.38,6.99) 106.38,5.48 105.75,4.86 102.37,4.86 J16.28
  L4_SIG2 w0.13: v1(106.38,6.99) 108.9,9.51 108.9,11.49 108.44,11.96 108.44,14.17 108.84,14.57 108.84,20.41 109.88,21.45 109.88,24.44 110.99,25.55 110.99,30.01 110.99,35.9 110.7,36.2 110.7,36.7 109.66,37.74 109.66,38.62 110.81,39.77 110.81,40.24 110.68,40.37 110.68,42.21 111.52,43.05 111.52,44.89 111.05,45.36 111.05,48.66 110.05,49.66 110.05,53.42 107.33,56.14 107.33,57.06 106.36,58.03 106.36,58.76 101.82,63.3 99.68,63.3 98.43,64.56 98.43,66.51 96.4,68.54 96.4,74.96 90.84,80.52 86.71,80.52 85.57,81.66 v1(84.71,81.66)
  BOTTOM w0.13: v1(83.76,73.07) 84.08,73.07 84.31,73.3 84.31,74.1 83.06,75.35 83.06,79.65 83.9,80.49 83.9,80.98 84.58,81.66 v1(84.71,81.66) 85.34,82.3 R382.2
AM437X_SPI0_SCLK: length 10.8
  TOP w0.13: U11.P23 81.48,73.99 81.89,73.99 v1(82.02,73.87)
  BOTTOM w0.13: R385.1 82.32,82.91 82.32,79.96 82.17,79.81 82.17,76.33 81.6,75.76 81.6,74.28 v1(82.02,73.87)
AM437X_SPI1_CS0: length 12.4
  TOP w0.13: R99.2 63.53,72.99 63.75,72.77 65.77,72.77 69.43,69.1 U11.A16
AM437X_SPI1_D1: length 9.8
  TOP w0.13: R111.2 65.08,69.82 65.4,69.49 65.4,69.49 66.67,69.49 68.69,67.48 73.01,67.48 U11.B13
AM437X_SPI1_SCLK: length 12
  TOP w0.13: U11.D16 74.63,69.1 74.63,68.62 v1(74.62,68.61)
  BOTTOM w0.13: R437.2 66.35,72.26 69.27,69.34 73.89,69.34 v1(74.62,68.61)
AM437X_UART0_CTSN: length 12.5
  TOP w0.13: U11.L25 79.19,75.18 79.81,75.8 79.81,80.61 80.83,81.64 80.83,82.1 81.66,82.93 81.66,85.47 81.15,85.98 R72.1
AM437X_UART0_RTSN: length 12.6
  TOP w0.13: R71.1 79.5,85.62 79.51,85.62 79.51,82 78.86,81.35 78.86,81.34 78.39,80.88 78.07,80.88 77.78,80.59 77.78,78.8 78.36,78.22 78.36,77.11 77.89,76.64 U11.J25
AM437X_UART0_RXD: length 10
  TOP w0.13: U11.K25 78.54,75.18 79.29,75.94 79.29,77.95 78.24,79 78.24,79.83 78.69,80.28 78.97,80.28 80.52,81.83 80.52,82.23 80.64,82.35 R89.1
AM437X_UART0_TXD: length 110.6
  TOP w0.13: R261.2 116.84,9.91 115.63,9.91 114.62,10.92 114.62,11.75 114.16,12.21 113.62,12.21 113.07,12.76 113.07,13.71 110.81,15.97 106.52,15.97 104.9,14.35 104.9,14.2 v1(103.68,12.98) ; U11.J24 77.58,74.61 77.58,75.47 77.63,75.52 77.63,76.8 78.13,77.29 78.13,78.13 77.54,78.71 77.54,80.72 78.02,81.2 78.27,81.2 78.55,81.47 78.55,81.91 v1(78.87,82.22) 78.74,82.35 R88.1
  L4_SIG2 w0.13: v1(78.87,82.22) 78.87,81.09 85.36,74.6 87.38,74.6 91.96,70.01 91.96,65.83 94.17,63.63 94.17,62.79 97.67,59.29 97.67,56.44 99.34,54.77 99.34,53.92 100.68,52.57 100.68,51.19 102.39,49.49 102.39,44.93 103.17,44.15 104.44,42.87 104.44,37.61 104.44,37.61 104.44,34.97 104.67,34.74 104.67,26.81 104.6,26.74 104.6,26.74 103.88,26.02 103.88,24.71 104.19,24.41 104.19,19.93 103.68,19.42 v1(103.68,12.98)
AM437X_VDDS: length 40.1
  TOP w0.13: v1(84.38,67.98) U11.W15
  TOP w0.203: U11.F20 76.41,71.22 v1(76.76,71.22) ; v1(76.99,62.86) 76.85,62.86 U11.G6 ; U11.H12 76.93,66.81 76.44,66.81 76.44,66.81 v1(76.26,66.81)
  TOP w0.254: v1(85.9,71.49) 85.39,71.41 U11.Y19 ; U11.P19 81.44,71.05 v1(81.63,70.86)
  L3_SIG1 w0.13: 87.31,65.98 86.8,66.49 85.53,66.49
  L3_SIG1 w0.254: 85.53,66.49 84.82,66.49 84.07,67.23 84.07,67.66 84.38,67.97 v1(84.38,67.98)
  L3_SIG1 w0.508: 103.48,67.46 v3(103.45,67.46) ; 103.48,67.46 104.52,67.46 105.03,66.95 v3(105.03,65.53) ; 103.48,67.46 102.9,66.88 99.46,66.88 97.92,65.34 87.95,65.34 87.31,65.98
  BOTTOM w0.381: C200.1 86.74,71.65 87.22,72.14 88.19,72.14 C199.1 ; C216.1 84.22,67.82 v1(84.38,67.98) 84.38,68.57 C210.1
  BOTTOM w0.457: v1(85.9,71.49) 86.73,71.49
  BOTTOM w0.508: v3(68.55,61.87) 69.56,61.87 R463.2 ; v3(105.03,65.53) 105.03,67.71 C214.1 103.94,67.95 v3(103.45,67.46) ; 86.73,71.49 C200.1
CAM0_GIO0: length 7.4
  BOTTOM w0.13: U38.5 133.02,90.93 132.26,91.69 130.81,91.69 130.43,91.31 129.67,91.31 129.67,93.6
CAM_MTR_EN: length 201.8
  TOP w0.13: v1(115.67,107.19) 116.59,106.27 116.59,104.77 117.79,103.57 117.79,98.13 115.15,95.49 v1(115.15,93.47) U6.22 ; v1(67.67,57.38) 67.67,57.99 69.13,59.45 69.58,59.45 70.6,60.46 72.11,60.46 72.46,60.11 72.57,60.11 U11.A2
  L3_SIG1 w0.13: v1(115.67,107.19) 108.33,107.19 103.38,112.14 71.67,112.14 70.92,111.38 66.18,111.38 63.19,108.38 59.43,108.38 56.13,105.08 49.41,105.08 v1(49.17,105.31) ; v1(67.67,57.38) 67.67,56.9 67.47,56.71 67.47,56.63 64.73,53.88 56.6,53.88 55.74,53.02 52.03,53.02 51.33,52.32 v1(40.21,52.32)
  L4_SIG2 w0.13: v1(60.13,101.71) 60.13,98.35 60.58,97.91 60.58,93.3 57.95,90.67 57.95,86.5 56.75,85.3 56.75,83.93 52.81,79.98 52.81,70.36 51.03,68.58 44.32,68.58 38.48,62.74 38.48,54.05 v1(40.21,52.32)
  BOTTOM w0.13: v1(49.17,105.31) 52.28,102.2 59.65,102.2 v1(60.13,101.71) ; R343.1 v1(115.15,93.47)
CAM_SRCCLK: length 96
  TOP w0.13: U11.C24 74.33,74.64 74.33,75.29 75.07,76.03 75.07,79.02 74.7,79.39 74.7,81.13 v1(74.42,81.41)
  L3_SIG1 w0.13: v1(74.42,81.41) 76.71,83.69 76.71,85.67 76.04,86.35 76.04,87.29 76.9,88.15 76.9,88.79 83.61,95.5 84.84,95.5 85.16,95.82 85.16,97.6 85.9,98.35 92.12,98.35 94.46,100.69 98.4,100.69 100.98,103.26 110.24,103.26 111.46,104.48 126.6,104.48 129.24,101.85 130.86,101.85 134.26,98.46 134.26,95.53 133.68,94.94 v1(133.68,88.27)
  BOTTOM w0.13: U38.4 v1(133.68,88.27)
CAN0_RXDF: length 108.1
  TOP w0.13: R248.2 88.29,9.4 v1(90.14,7.54)
  L4_SIG2 w0.13: v1(78.7,84.8) 79.66,83.84 79.66,82.8 79.34,82.48 79.34,81.05 85.56,74.83 87.49,74.83 89.78,72.54 90,72.54 92.27,70.27 92.27,65.96 94.47,63.75 94.47,62.92 97.98,59.42 97.98,56.56 99.71,54.83 99.71,53.98 100.99,52.7 100.99,52.09 100.99,51.32 102.69,49.62 102.69,45.06 103.48,44.28 104.75,43 104.75,37.48 104.75,35.1 105.03,34.82 105.03,26.19 105.33,25.89 105.33,25.42 105,25.08 105,24.03 105.6,23.42 105.6,22.76 104.89,22.05 104.89,20.19 104.07,19.38 104.07,13.66 104.65,13.08 104.65,10.92 103.06,9.32 100.99,9.32 100.48,8.81 97.25,8.81 97.05,9.02 93.83,9.02 92.35,7.54 v1(90.14,7.54)
  BOTTOM w0.13: R386.2 78.7,84.11 v1(78.7,84.8)
CAN0_RXDF_PR1_EDC_LATCH0_IN: length 3.7
  TOP w0.13: J16.41 87.35,8.35 R248.1 R247.1
CAN0_TXDF: length 108.3
  TOP w0.13: R246.2 v1(85.09,10.54)
  L4_SIG2 w0.13: v1(76.2,84.86) 77.61,83.45 77.61,81.47 79.45,79.63 79.45,78.53 82.24,75.75 82.75,75.75 84.6,73.9 86.77,73.9 91.04,69.63 91.04,65.45 93.24,63.24 93.24,62.41 96.74,58.91 96.74,56.05 98.41,54.38 98.41,53.53 99.76,52.19 99.76,50.81 101.3,49.27 101.3,40.21 102.91,38.6 103.08,38.6 103.52,38.16 103.52,34.53 103.68,34.37 103.68,27.12 102.76,26.21 102.76,13.59 100.57,11.41 100.57,9.87 100.29,9.59 97.35,9.59 97.3,9.63 86,9.63 v1(85.09,10.54)
  BOTTOM w0.13: v1(76.2,84.86) 76.07,84.73 C177.1 R387.2
CAN0_TXDF_PR1_EDC_LATCH1_IN: length 3.8
  TOP w0.13: R245.1 R246.1 85.09,6.1 J16.43
CAP_VDD_RTC: length 17.1
  TOP w0.13: U11.AD3 87.94,60.96 91.49,60.96
  TOP w0.508: C71.1 100.71,57 98.58,59.13 96.38,59.13 94.56,60.96 91.49,60.96
DDR_A0: length 96.2
  TOP w0.102: U21.N3 v1(92.01,30.82) ; U11.N1 80.48,58.83 80.52,58.8 v1(80.52,58.27) ; v1(84.28,45.62) 83.85,45.19 83.85,33.5 83.39,33.05 83.39,31.05 79.13,26.79 74.62,26.79 73.66,27.76 73.66,29.95 72.95,30.66 72.95,30.91 v1(72.94,30.92) 72.84,30.82 U20.N3
  L3_SIG1 w0.102: v1(84.28,45.62) 83.85,46.04 83.85,46.24 83.81,46.28 83.81,46.81 83.57,47.06 81.41,47.06 81.13,47.33 81.13,47.5 81.26,47.63 81.26,47.8 81.14,47.92 80.98,47.92 80.85,47.79 80.68,47.79 80.49,47.97 80.49,48.27 80.61,48.39 80.95,48.39 81.07,48.5 81.07,48.67 80.95,48.79 80.43,48.79 80.31,48.91 80.31,50.35 80.43,50.47 81.31,50.47 81.43,50.59 81.43,50.76 81.31,50.88 80.16,50.88 80.03,51.01 80.03,51.3 80.36,51.63 80.36,52.91 80.76,53.31 81.22,53.77 82.4,53.77 82.6,53.97 82.6,55.29 82.26,55.63 82.26,55.83 82.14,55.95 81.81,55.95 81.69,56.07 81.69,56.24 81.81,56.36 82.14,56.36 82.26,56.48 82.26,56.67 81.36,57.57 81.36,59.01 81.79,59.44 82.68,59.44 82.89,59.65 82.89,59.86 82.69,60.06 82.43,60.06 82.31,60.18 82.31,60.33 82.19,60.45 82.03,60.45 81.91,60.33 81.91,60.18 81.79,60.06 81.12,60.06 80.52,59.45 v1(80.52,58.27)
  L4_SIG2 w0.102: v1(72.94,30.92) 72.94,31.06 73.66,31.77 75.5,31.77 75.99,32.27 76.27,32.27 76.39,32.15 76.39,31.95 76.51,31.83 76.67,31.83 76.79,31.95 76.79,32.15 76.91,32.27 78.11,32.27 78.3,32.08 79.11,32.08 79.23,31.96 79.23,30.93 79.35,30.81 79.52,30.81 79.64,30.93 79.64,31.96 79.76,32.08 79.93,32.08 80.05,31.96 80.05,30.93 80.16,30.81 80.33,30.81 80.45,30.93 80.45,31.96 80.57,32.08 81.27,32.08 81.59,31.75 85.59,31.75 87.25,30.1 88.52,30.1 89.28,30.86 89.79,30.86 89.99,31.06 91.76,31.06 v1(92.01,30.82)
  BOTTOM w0.102: v1(92.01,30.82) 92.55,30.82 93.06,30.31 93.06,29.78 92.71,29.44 92.71,28.24 94.61,26.34 R528.2
DDR_A1: length 95.1
  TOP w0.102: U20.P7 75.24,30.02 v1(74.79,29.57) 74.37,29.57 74.14,29.34 74.14,28.04 74.51,27.68 74.88,27.68 74.99,27.58 78.01,27.58 78.04,27.61 78.56,27.61 82.58,31.62 82.58,33.38 83.03,33.84 83.03,45.84 83.01,45.86 v1(83.01,45.89) ; R218.2 91.8,24.92 91.8,27.46 92.33,27.99 92.33,28.96 92.65,29.28 v1(92.65,30.02) 92.65,30.02 92.66,30.02 U21.P7 ; U11.L1 v1(79.19,58.81)
  L3_SIG1 w0.102: v1(83.01,45.89) 83.01,44.27 82.71,43.97 82.43,43.97 82.31,43.85 82.31,42.7 82.18,42.58 82.02,42.58 81.9,42.69 81.9,43.85 81.78,43.97 81.61,43.97 81.49,43.85 81.49,42.71 81.39,42.61 81.22,42.61 81.09,42.74 81.09,43.85 80.97,43.97 80.8,43.97 80.68,43.85 80.68,42.71 80.58,42.61 80.41,42.61 80.27,42.74 80.27,43.85 80.16,43.97 79.83,43.97 79.52,44.27 79.52,44.94 79.64,45.05 79.64,46.14 79.27,46.51 78.55,46.51 78.46,46.42 78.46,45.82 78.34,45.7 78.26,45.7 77.2,45.7 77.08,45.82 77.08,46.14 76.9,46.32 76.08,46.32 75.77,46.63 75.77,50.62 78.99,53.85 78.99,58.62 v1(79.19,58.81)
  L4_SIG2 w0.102: v1(74.79,29.57) 74.14,28.91 74.14,27.54 74.44,27.24 77.76,27.24 78.51,27.99 81.25,27.99 81.37,28.11 81.37,28.41 81.48,28.52 81.65,28.52 81.77,28.41 81.77,28.11 81.89,27.99 82.06,27.99 82.18,28.11 82.18,28.41 82.3,28.52 82.47,28.52 82.58,28.41 82.58,28.11 82.7,27.99 85.29,27.99 86.67,26.62 88.9,26.62 89.48,27.2 89.48,28.4 90.96,29.87 90.96,30.19 91.19,30.43 91.53,30.43 91.94,30.02 v1(92.65,30.02)
DDR_A2: length 99.9
  TOP w0.102: v1(79.15,51.09) 79.15,53.3 79.03,53.42 78.67,53.42 78.55,53.54 78.55,53.71 78.67,53.83 79.03,53.83 79.15,53.95 79.15,55.06 79.38,55.3 79.38,55.71 79.27,55.83 79.03,55.83 78.91,55.95 78.91,56.12 79.03,56.23 79.27,56.23 79.38,56.35 79.38,56.52 79.27,56.64 79.03,56.64 78.91,56.76 78.91,56.93 79.03,57.05 79.27,57.05 79.38,57.17 79.38,57.37 79.06,57.7 79.06,58.36 78.78,58.64 78.78,59.09 78.89,59.21 78.89,59.71 U11.L2 ; U21.P3 91.35,30.02 91.36,30.02 v1(91.36,30.02) ; U20.P3 72.31,30.27 v1(72.7,30.27) 73.42,29.54 73.42,27.41 74.45,26.39 79.3,26.39 83.8,30.89 83.8,31.35 83.92,31.47 84.13,31.47 84.25,31.59 84.25,31.76 84.13,31.87 83.92,31.87 83.8,31.99 83.8,32.83 84.28,33.3 v1(84.28,44.83)
  L3_SIG1 w0.102: v1(91.36,30.02) 91.36,30.76 90.35,31.78 87.4,31.78 86.87,31.24 86.87,30.51 86.49,30.12 85.51,30.12 85.39,30.24 85.39,30.64 85.27,30.76 85.11,30.76 84.99,30.64 84.99,30.24 84.87,30.12 84.7,30.12 84.58,30.24 84.58,30.69 84.46,30.81 84.29,30.81 84.17,30.69 84.17,30.24 84.05,30.12 83.76,30.12 83.64,30.24 83.64,31.56 83.53,31.67 83.36,31.67 83.24,31.55 83.24,30.28 83.03,30.07 82.77,30.07 82.65,30.19 82.65,30.74 82.53,30.86 82.36,30.86 82.24,30.74 82.24,30.19 82.12,30.07 81.95,30.07 81.83,30.19 81.83,30.74 81.71,30.86 81.55,30.86 81.43,30.74 81.43,30.19 81.31,30.07 81.14,30.07 81.02,30.19 81.02,30.74 80.9,30.86 80.73,30.86 80.61,30.74 80.61,30.19 80.49,30.07 80.33,30.07 80.21,30.19 80.21,30.74 80.09,30.86 79.92,30.86 79.8,30.74 79.8,30.19 79.68,30.07 78.05,30.07 77.41,30.71 76.52,30.71 76.37,30.86 75.56,30.86 75.25,30.55 75.25,30.25 74.99,29.99 72.98,29.99 v1(72.7,30.27) ; v1(84.28,44.83) 83.85,44.83 83.45,45.24 83.45,46.07 83.02,46.5 82.6,46.5 82.48,46.38 82.48,44.52 82.36,44.4 82.19,44.4 82.07,44.52 82.07,46.38 81.95,46.5 81.78,46.5 81.67,46.38 81.67,44.52 81.55,44.4 81.38,44.4 81.26,44.52 81.26,46.38 81.14,46.5 80.75,46.5 80.54,46.71 80.54,46.88 80.67,47.01 80.67,47.18 80.55,47.3 80.38,47.3 80.25,47.17 80.09,47.17 79.97,47.29 79.97,47.46 80.1,47.58 80.1,47.75 79.98,47.87 79.81,47.87 79.68,47.74 79.51,47.74 79.25,48.01 79.25,48.33 79.13,48.44 78.87,48.44 78.75,48.56 78.75,48.73 78.87,48.85 79.13,48.85 79.25,48.97 79.25,50.99 v1(79.15,51.09)
  BOTTOM w0.102: v1(91.36,30.02) 91.37,30.02 91.37,28.92 91.7,28.59 91.7,26.41 R530.2
DDR_A3: length 96
  TOP w0.102: U20.N2 v1(70.86,30.42) ; v1(89.54,30.44) 89.91,30.82 U21.N2 ; v1(81.59,53.13) 81.37,53.35 81.01,53.35 80.62,53.74 80.62,55.78 81.37,56.53 81.37,59.15 81.44,59.22 81.44,59.69 U11.P2
  L3_SIG1 w0.102: v1(81.59,53.13) 81.9,52.82 81.9,50.48 81.69,50.27 81.69,50.06 81.81,49.94 82.3,49.94 82.41,49.83 82.41,49.66 82.29,49.54 81.81,49.54 81.69,49.42 81.69,49.25 81.81,49.13 82.46,49.13 82.58,49.01 82.58,48.84 82.46,48.73 81.81,48.73 81.69,48.61 81.69,47.8 82.03,47.47 84.82,47.47 85.18,47.1 85.18,46.22 84.9,45.94 v1(84.9,45.02)
  L4_SIG2 w0.102: v1(89.54,30.44) 89.03,29.93 89.03,29.46 88.65,29.08 88.29,29.08 87.65,29.73 86.67,29.73 86.47,29.53 86.3,29.53 86.18,29.64 86.18,29.81 86.38,30.01 86.38,30.18 86.26,30.3 86.09,30.3 85.89,30.1 85.72,30.1 85.6,30.22 85.6,30.39 85.8,30.59 85.8,30.76 85.45,31.12 84.82,31.12 84.7,31 84.7,30.19 84.58,30.07 84.41,30.07 84.29,30.19 84.29,31 84.18,31.12 84.01,31.12 83.89,31 83.89,30.19 83.77,30.07 83.6,30.07 83.48,30.19 83.48,31 83.36,31.12 83.19,31.12 83.08,31 83.08,30.19 82.96,30.07 82.79,30.07 82.67,30.19 82.67,31 82.55,31.12 82.38,31.12 82.26,31 82.26,30.19 82.14,30.07 81.98,30.07 81.86,30.19 81.86,31 81.74,31.12 81.23,31.12 80.52,30.4 78.98,30.4 78.7,30.68 78.7,31.39 78.42,31.68 77.92,31.68 77.77,31.53 77.77,31.52 77.53,31.29 75.25,31.29 74.88,30.91 73.92,30.91 73.81,30.8 73.4,30.8 73.11,30.5 73.11,30.06 72.91,29.87 72.49,29.87 71.93,30.42 v1(70.86,30.42)
  BOTTOM w0.102: v1(70.86,30.42) 71.35,30.42 73.01,32.08 75.55,32.08 75.96,32.49 77.8,32.49 78.14,32.14 80.56,32.14 83.65,35.24 83.65,35.6 83.77,35.72 84.1,35.72 84.22,35.84 84.22,36.01 84.1,36.13 83.77,36.13 83.65,36.25 83.65,36.41 83.77,36.53 84.1,36.53 84.22,36.65 84.22,36.82 84.1,36.94 83.77,36.94 83.65,37.06 83.65,37.23 83.77,37.35 84.1,37.35 84.22,37.47 84.22,37.63 84.1,37.75 83.77,37.75 83.65,37.87 83.65,38.04 83.77,38.16 84.1,38.16 84.22,38.28 84.22,38.45 84.1,38.57 83.77,38.57 83.65,38.68 83.65,38.85 83.77,38.97 84.1,38.97 84.22,39.09 84.22,39.26 84.1,39.38 83.77,39.38 83.65,39.5 83.65,39.67 83.77,39.79 84.1,39.79 84.22,39.9 84.22,40.07 84.1,40.19 83.77,40.19 83.65,40.31 83.65,40.48 83.77,40.6 84.1,40.6 84.22,40.72 84.22,40.89 84.1,41 83.77,41 83.65,41.12 83.65,41.29 83.77,41.41 84.1,41.41 84.22,41.53 84.22,41.7 84.1,41.82 83.77,41.82 83.65,41.94 83.65,42.1 83.77,42.22 84.1,42.22 84.22,42.34 84.22,42.51 84.1,42.63 83.77,42.63 83.65,42.75 83.65,42.92 83.77,43.04 84.47,43.04 84.6,43.17 84.6,43.34 84.49,43.44 83.77,43.44 83.65,43.56 83.65,43.9 83.82,44.07 84.71,44.07 84.9,44.26 v1(84.9,45.02) ; R535.2 86.61,27.16 88.49,29.03 88.64,29.03 88.95,29.34 88.95,29.86 v1(89.54,30.44)
DDR_A4: length 93.9
  TOP w0.102: v1(75.65,29.63) 76.04,30.02 U20.P8 76.06,30.17 76.37,30.48 77,30.48 77.15,30.63 77.49,30.63 77.54,30.58 78.31,30.58 78.88,31.15 78.88,31.32 78.6,31.6 78.6,31.77 78.72,31.89 78.89,31.89 79.17,31.61 79.33,31.61 79.85,32.13 79.85,32.36 80.03,32.53 80.25,32.53 80.43,32.71 80.43,33.77 80.43,34.11 80.95,34.63 80.95,45.05 v1(80.57,45.43) ; v1(80.86,56.68) 81.13,56.96 U11.P1 ; v1(94.34,29.59) U21.P8
  L3_SIG1 w0.102: v1(80.57,45.43) 80.57,45.92 79.1,47.4 78.96,47.4 78.91,47.34 78.91,47.05 78.79,46.93 78.62,46.93 78.5,47.05 78.5,47.34 78.38,47.46 77.96,47.46 77.84,47.58 77.84,48.12 77.72,48.24 77.55,48.24 77.43,48.12 77.43,47.58 77.31,47.46 77.09,47.46 76.98,47.34 76.98,46.85 76.86,46.74 76.69,46.74 76.57,46.85 76.57,47.34 76.45,47.46 76.31,47.46 76.17,47.59 76.17,47.89 76.28,47.99 76.97,47.99 77.06,48.09 77.06,48.26 76.92,48.4 76.29,48.4 76.17,48.51 76.17,48.69 76.29,48.81 77.38,48.81 77.49,48.92 77.49,49.09 77.37,49.21 76.28,49.21 76.17,49.32 76.17,49.51 76.29,49.62 77.28,49.62 77.39,49.73 77.39,49.91 77.27,50.03 76.42,50.03 76.3,50.14 76.3,50.52 76.58,50.8 76.75,50.8 77.08,50.46 77.29,50.46 77.39,50.57 77.39,50.73 77.01,51.11 77.01,51.27 77.12,51.39 77.3,51.39 77.46,51.23 77.63,51.23 77.75,51.35 77.75,51.52 77.58,51.69 77.58,51.86 77.71,51.98 77.86,51.98 78.04,51.8 78.21,51.8 78.32,51.92 78.32,52.09 78.16,52.25 78.16,52.43 78.28,52.55 78.44,52.55 78.61,52.38 78.78,52.38 78.9,52.5 78.9,52.67 78.73,52.84 78.73,53.01 78.85,53.13 78.98,53.13 79.08,53.03 79.25,53.03 79.37,53.15 79.37,53.32 79.32,53.37 79.32,53.54 79.48,53.7 79.48,54.07 79.6,54.19 80.4,54.19 80.52,54.3 80.52,54.46 80.38,54.59 79.55,54.59 79.44,54.71 79.44,54.88 79.56,55 80.54,55 80.64,55.1 80.64,55.29 80.53,55.41 79.5,55.41 79.4,55.51 79.4,55.69 79.53,55.81 80.51,55.81 80.64,55.94 80.64,56.1 80.52,56.22 79.6,56.22 79.48,56.34 79.48,56.97 79.6,57.09 79.73,57.09 79.85,56.97 79.85,56.64 79.97,56.52 80.13,56.52 80.25,56.64 80.25,56.97 80.37,57.09 80.46,57.09 v1(80.86,56.68)
  L4_SIG2 w0.102: v1(94.34,29.59) 93.52,30.41 93.51,30.41 93.18,30.41 93.13,30.45 92.22,30.45 92.18,30.41 91.84,30.41 91.62,30.63 91.11,30.63 90.75,30.28 90.75,30.05 89.28,28.58 89.28,27.28 89.09,27.09 86.8,27.09 84.83,29.06 80.02,29.06 79.9,28.94 79.9,28.52 79.78,28.4 79.62,28.4 79.5,28.52 79.5,28.94 79.38,29.06 78.82,29.06 77.49,27.74 75.46,27.74 75.23,27.97 75.23,29.21 v1(75.65,29.63)
  BOTTOM w0.102: v1(94.34,29.59) 94.74,29.19 95.94,29.19 96.63,28.51 99.38,28.51 R520.2
DDR_A5: length 94.5
  TOP w0.102: U11.R5 82,61.95 82.13,61.82 82.13,61.17 82.34,60.96 82.62,60.96 v1(82.91,61.25) ; v1(70.84,29.6) U20.P2 ; U21.P2 89.95,30.02 v1(90.32,30.39)
  L3_SIG1 w0.102: v1(70.84,29.6) 71.7,28.75 72.9,28.75 73.31,29.16 74.62,29.16 74.62,29.16 74.96,29.16 74.96,29.16 75.44,29.16 75.49,29.21 75.86,29.21 76.06,29.4 76.06,29.79 76.3,30.02 76.63,30.02 76.87,29.79 76.87,29.41 77.32,28.96 78.36,28.96 78.64,28.68 79.03,28.68 79.15,28.56 79.15,28.1 79.27,27.98 79.44,27.98 79.56,28.1 79.56,28.56 79.68,28.68 79.84,28.68 79.96,28.56 79.96,28.1 80.08,27.98 80.25,27.98 80.37,28.1 80.37,28.56 80.49,28.68 80.66,28.68 80.78,28.56 80.78,28.1 80.9,27.98 81.06,27.98 81.18,28.1 81.18,28.56 81.3,28.68 81.47,28.68 81.59,28.56 81.59,28.1 81.71,27.98 81.88,27.98 82,28.1 82,28.56 82.11,28.68 82.28,28.68 82.4,28.56 82.4,28.1 82.52,27.98 82.69,27.98 82.81,28.1 82.81,28.56 82.93,28.68 83.1,28.68 83.21,28.56 83.21,28.1 83.33,27.98 83.5,27.98 83.62,28.1 83.62,28.56 83.74,28.68 83.91,28.68 84.03,28.56 84.03,28.1 84.15,27.98 84.31,27.98 84.43,28.1 84.43,28.56 84.55,28.68 84.72,28.68 84.84,28.56 84.84,28.1 84.96,27.98 85.13,27.98 85.25,28.1 85.25,28.56 85.37,28.68 85.53,28.68 85.65,28.56 85.65,28.1 85.77,27.98 85.94,27.98 86.06,28.1 86.06,28.56 86.18,28.68 87.8,28.68 88.31,29.18 88.69,29.18 89.15,29.64 89.15,29.77 89.39,30.01 89.94,30.01 v1(90.32,30.39)
  L4_SIG2 w0.102: v1(86.46,42.16) 86.99,42.16 87.23,42.4 87.23,42.66 87.35,42.78 88.92,42.78 89.05,42.91 89.05,43.08 88.94,43.19 87.35,43.19 87.23,43.31 87.23,43.48 87.35,43.59 89.32,43.59 89.43,43.71 89.43,43.88 89.32,44 87.35,44 87.23,44.12 87.23,46.71 86.56,47.38 86.56,52.73 84.58,54.71 84.38,54.71 83.73,55.36 83.73,58.6 82.46,59.87 82.46,60.78 82.91,61.24 v1(82.91,61.25)
  BOTTOM w0.102: R533.2 88.9,26.62 89.46,27.18 90.05,27.18 90.33,27.46 90.33,27.8 90.32,27.82 v1(90.32,30.39) ; v1(86.46,42.16) 84.68,40.38 84.68,35.36 81.02,31.69 78.2,31.69 77.76,32.13 76.15,32.13 75.81,31.79 73.17,31.79 70.98,29.6 v1(70.84,29.6)
